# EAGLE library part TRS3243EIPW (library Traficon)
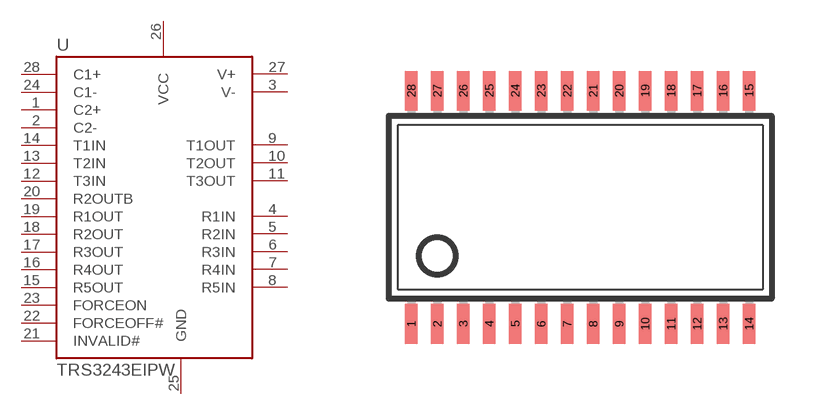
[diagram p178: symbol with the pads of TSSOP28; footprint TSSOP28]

Designator prefix U

## TRS3243EIPW  [TSSOP28]
1  C2+  pas
2  C2-  pas
3  V-  pwr
4  R1IN  in
5  R2IN  in
6  R3IN  in
7  R4IN  in
8  R5IN  in
9  T1OUT  out
10  T2OUT  out
11  T3OUT  out
12  T3IN  in
13  T2IN  in
14  T1IN  in
15  R5OUT  out
16  R4OUT  out
17  R3OUT  out
18  R2OUT  out
19  R1OUT  out
20  R2OUTB  out
21  INVALID#  out
22  FORCEOFF#  in
23  FORCEON  in
24  C1-  pas
25  GND  sup
26  VCC  sup
27  V+  pwr
28  C1+  pas

## Footprint TSSOP28 (pad centres in mm)
Thin Shrink Small Outline Plastic 28 MAX3223-MAX3243.pdf
smd 0.305 x 0.991: 1 -4.225,-2.918; 2 -3.575,-2.918; 3 -2.925,-2.918; 4 -2.275,-2.918; 5 -1.625,-2.918; 6 -0.975,-2.918; 7 -0.325,-2.918; 8 0.325,-2.918; 9 0.975,-2.918; 10 1.625,-2.918; 11 2.275,-2.918; 12 2.925,-2.918; 13 3.575,-2.918; 14 4.225,-2.918; 15 4.225,2.918; 16 3.575,2.918; 17 2.925,2.918; 18 2.275,2.918; 19 1.625,2.918; 20 0.975,2.918; 21 0.325,2.918; 22 -0.325,2.918; 23 -0.975,2.918; 24 -1.625,2.918; 25 -2.275,2.918; 26 -2.925,2.918; 27 -3.575,2.918; 28 -4.225,2.918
